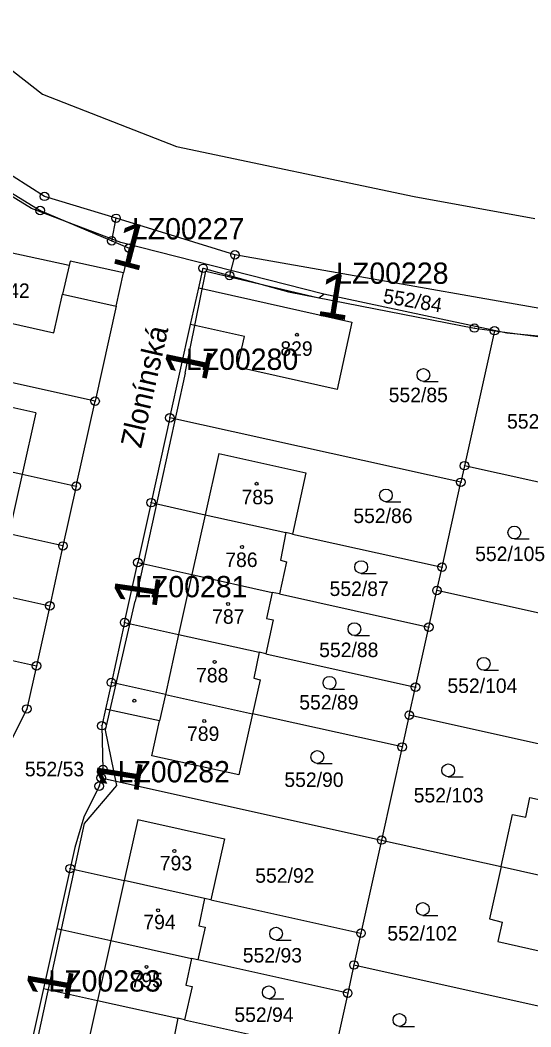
# Model space of a CAD drawing. Extents: x -738131 to -734179, y -1033447 to -1030078.
# Drawn here: x -735624.4 to -735564.5, y -1032052.3 to -1031934.1 of the extents above; entities that cross this region are included whole.
import ezdxf

# ---------------------------------------------------------------- set-up
doc = ezdxf.new("R2010")
doc.units = 0
for name, color, linetype in [('ftf_2010', 7, 'Continuous'), ('ftf_3010', 7, 'Continuous'), ('ftf_3010_ftf_3010_gtda_3015_gtda_3015_1', 7, 'Continuous'), ('ftf_nu', 7, 'Continuous'), ('Vrstva 1', 7, 'Continuous'), ('Vrstva 2', 7, 'Continuous'), ('Vrstva 3', 7, 'Continuous'), ('Vrstva 4', 7, 'Continuous'), ('Vrstva 5', 7, 'Continuous'), ('Vrstva 8', 7, 'Continuous')]:
    doc.layers.add(name, color=color, linetype=linetype)

msp = doc.modelspace()

# ---------------------------------------------------------------- linework, layer by layer
at = {"layer": 'ftf_2010'}
for points in [[(-735612.61, -1031960.22), (-735623.09, -1031956.22), (-735631.82, -1031950.86), (-735637.01, -1031946.51), (-735639.19, -1031944.26)], [(-735588.76, -1031966.29), (-735612.61, -1031960.22)], [(-735605.04, -1031975.54), (-735602.63, -1031963.58), (-735589.35, -1031966.7), (-735588.76, -1031966.29)], [(-735561.58, -1031971.42), (-735567.29, -1031970.85), (-735588.76, -1031966.29)], [(-735605.04, -1031975.54), (-735610.94, -1032002.29)], [(-735613.07, -1032023.94), (-735614.43, -1032017.46), (-735610.94, -1032002.29)], [(-735621.24, -1032048.4), (-735616.9, -1032028.4), (-735613.07, -1032023.94)], [(-735626.37, -1032072.12), (-735621.24, -1032048.4)]]:
    msp.add_lwpolyline(points, dxfattribs=at)
at = {"layer": 'Vrstva 1'}
for points in [[(-735632.99, -1031934.13), (-735621.82, -1031942.82)], [(-735621.82, -1031942.82), (-735606.06, -1031948.94)], [(-735621.58, -1031954.81), (-735632.67, -1031947.8)], [(-735606.06, -1031948.94), (-735578.16, -1031954.83)], [(-735632.24, -1031950.25), (-735622.08, -1031956.47)], [(-735613.18, -1031957.38), (-735621.58, -1031954.81)], [(-735578.16, -1031954.83), (-735563.98, -1031957.41)], [(-735622.08, -1031956.47), (-735613.69, -1031960.02)], [(-735613.69, -1031960.02), (-735613.18, -1031957.38)], [(-735599.21, -1031961.66), (-735613.18, -1031957.38)], [(-735613.69, -1031960.02), (-735611.65, -1031960.88)], [(-735618.67, -1031962.92), (-735630.47, -1031960.38)], [(-735611.65, -1031960.88), (-735612.3, -1031963.79)], [(-735618.56, -1031962.41), (-735618.67, -1031962.92)], [(-735612.3, -1031963.79), (-735618.56, -1031962.41)], [(-735599.21, -1031961.66), (-735599.84, -1031964.11)], [(-735549.41, -1031970.43), (-735599.21, -1031961.66)], [(-735603.47, -1031965.55), (-735602.96, -1031963.25)], [(-735602.96, -1031963.25), (-735599.84, -1031964.11)], [(-735613.16, -1031967.7), (-735612.3, -1031963.79)], [(-735599.84, -1031964.11), (-735592.94, -1031966)], [(-735604.42, -1031969.83), (-735603.47, -1031965.55)], [(-735603.47, -1031965.55), (-735585.48, -1031969.59)], [(-735620.49, -1031970.84), (-735619.45, -1031966.29)], [(-735619.45, -1031966.29), (-735613.16, -1031967.7)], [(-735592.94, -1031966), (-735571.09, -1031970.26)], [(-735632.16, -1031968.19), (-735620.49, -1031970.84)], [(-735613.16, -1031967.7), (-735615.64, -1031978.85)], [(-735606.85, -1031980.8), (-735604.42, -1031969.83)], [(-735598.1, -1031971.24), (-735604.42, -1031969.83)], [(-735585.48, -1031969.59), (-735587.19, -1031977.48)], [(-735568.73, -1031970.57), (-735572.25, -1031986.41)], [(-735571.09, -1031970.26), (-735568.73, -1031970.57)], [(-735568.73, -1031970.57), (-735549.83, -1031973.07)], [(-735615.64, -1031978.85), (-735648.83, -1031971.47)], [(-735598.91, -1031974.87), (-735598.1, -1031971.24)], [(-735587.19, -1031977.48), (-735598.91, -1031974.87)], [(-735622.59, -1031980.2), (-735632.85, -1031977.94)], [(-735617.85, -1031988.81), (-735615.64, -1031978.85)], [(-735622.59, -1031980.2), (-735624.19, -1031987.4)], [(-735606.85, -1031980.8), (-735609.06, -1031990.75)], [(-735572.68, -1031988.36), (-735606.85, -1031980.8)], [(-735633.71, -1031985.28), (-735624.19, -1031987.4)], [(-735601.12, -1031984.97), (-735602.71, -1031992.16)], [(-735601.12, -1031984.97), (-735590.89, -1031987.24)], [(-735572.25, -1031986.41), (-735572.68, -1031988.36)], [(-735540.03, -1031993.56), (-735572.25, -1031986.41)], [(-735624.19, -1031987.4), (-735617.85, -1031988.81)], [(-735590.89, -1031987.24), (-735592.47, -1031994.43)], [(-735574.89, -1031998.32), (-735572.68, -1031988.36)], [(-735617.85, -1031988.81), (-735619.41, -1031995.83)], [(-735609.06, -1031990.75), (-735610.61, -1031997.78)], [(-735609.06, -1031990.75), (-735602.71, -1031992.16)], [(-735602.71, -1031992.16), (-735593.23, -1031994.26)], [(-735593.23, -1031994.26), (-735593.88, -1031997.51)], [(-735592.47, -1031994.43), (-735593.23, -1031994.26)], [(-735619.41, -1031995.83), (-735625.76, -1031994.42)], [(-735592.47, -1031994.43), (-735574.89, -1031998.32)], [(-735619.41, -1031995.83), (-735620.96, -1032002.86)], [(-735612.17, -1032004.81), (-735610.61, -1031997.78)], [(-735610.61, -1031997.78), (-735604.27, -1031999.19)], [(-735593.15, -1031997.68), (-735594, -1032001.46)], [(-735593.88, -1031997.51), (-735593.15, -1031997.68)], [(-735575.49, -1032001.05), (-735574.89, -1031998.32)], [(-735604.27, -1031999.19), (-735594.84, -1032001.28)], [(-735594.84, -1032001.28), (-735595.51, -1032004.33)], [(-735594, -1032001.46), (-735594.84, -1032001.28)], [(-735576.45, -1032005.35), (-735575.49, -1032001.05)], [(-735561.39, -1032004.18), (-735575.49, -1032001.05)], [(-735627.33, -1032001.45), (-735620.96, -1032002.86)], [(-735594, -1032001.46), (-735576.45, -1032005.35)], [(-735620.96, -1032002.86), (-735622.52, -1032009.89)], [(-735612.17, -1032004.81), (-735613.73, -1032011.84)], [(-735612.17, -1032004.81), (-735605.83, -1032006.22)], [(-735594.72, -1032004.5), (-735595.58, -1032008.49)], [(-735595.51, -1032004.33), (-735594.72, -1032004.5)], [(-735578.01, -1032012.39), (-735576.45, -1032005.35)], [(-735605.83, -1032006.22), (-735596.38, -1032008.31)], [(-735628.89, -1032008.48), (-735622.52, -1032009.89)], [(-735596.38, -1032008.31), (-735597, -1032011.35)], [(-735595.58, -1032008.49), (-735596.38, -1032008.31)], [(-735595.58, -1032008.49), (-735578.01, -1032012.39)], [(-735622.52, -1032009.89), (-735623.65, -1032014.96)], [(-735613.73, -1032011.84), (-735614.42, -1032014.97)], [(-735607.38, -1032013.25), (-735613.73, -1032011.84)], [(-735596.24, -1032011.52), (-735597.14, -1032015.52)], [(-735597, -1032011.35), (-735596.24, -1032011.52)], [(-735578.74, -1032015.68), (-735578.01, -1032012.39)], [(-735607.38, -1032013.25), (-735597.14, -1032015.52)], [(-735623.65, -1032014.96), (-735625.96, -1032019.58)], [(-735614.42, -1032014.97), (-735614.85, -1032016.92)], [(-735608.07, -1032016.35), (-735614.42, -1032014.97)], [(-735597.14, -1032015.52), (-735598.74, -1032022.69)], [(-735579.57, -1032019.42), (-735597.14, -1032015.52)], [(-735608.98, -1032020.44), (-735608.07, -1032016.35)], [(-735578.74, -1032015.68), (-735579.57, -1032019.42)], [(-735546.53, -1032022.85), (-735578.74, -1032015.68)], [(-735614.85, -1032016.92), (-735614.71, -1032022.06)], [(-735579.57, -1032019.42), (-735581.99, -1032030.34)], [(-735598.74, -1032022.69), (-735608.98, -1032020.44)], [(-735614.71, -1032022.06), (-735614.93, -1032023.04)], [(-735614.93, -1032023.04), (-735615.15, -1032024.01)], [(-735614.93, -1032023.04), (-735581.99, -1032030.34)], [(-735615.15, -1032024.01), (-735616.96, -1032027.64)], [(-735565.07, -1032027.66), (-735564.59, -1032025.33)], [(-735564.59, -1032025.33), (-735555.21, -1032027.4)], [(-735567.95, -1032033.46), (-735566.6, -1032027.35)], [(-735566.6, -1032027.35), (-735565.07, -1032027.66)], [(-735616.96, -1032027.64), (-735618.03, -1032031.22)], [(-735610.63, -1032027.93), (-735612.23, -1032035.1)], [(-735610.63, -1032027.93), (-735600.44, -1032030.2)], [(-735600.44, -1032030.2), (-735602.04, -1032037.36)], [(-735581.99, -1032030.34), (-735584.41, -1032041.27)], [(-735581.99, -1032030.34), (-735567.95, -1032033.46)], [(-735618.03, -1032031.22), (-735618.57, -1032033.69)], [(-735618.57, -1032033.69), (-735620.14, -1032040.72)], [(-735618.57, -1032033.69), (-735612.23, -1032035.1)], [(-735567.95, -1032033.46), (-735569.31, -1032039.58)], [(-735567.95, -1032033.46), (-735549.77, -1032037.5)], [(-735602.79, -1032037.19), (-735612.23, -1032035.1)], [(-735602.79, -1032037.19), (-735603.45, -1032040.41)], [(-735602.04, -1032037.36), (-735602.79, -1032037.19)], [(-735602.04, -1032037.36), (-735584.41, -1032041.27)], [(-735569.31, -1032039.58), (-735567.83, -1032039.96)], [(-735567.83, -1032039.96), (-735568.33, -1032042.23)], [(-735620.14, -1032040.72), (-735621.7, -1032047.76)], [(-735620.14, -1032040.72), (-735613.79, -1032042.13)], [(-735602.73, -1032040.56), (-735603.58, -1032044.39)], [(-735603.45, -1032040.41), (-735602.73, -1032040.56)], [(-735584.41, -1032041.27), (-735585.24, -1032045)], [(-735613.79, -1032042.13), (-735604.32, -1032044.23)], [(-735568.33, -1032042.23), (-735558.98, -1032044.34)], [(-735604.32, -1032044.23), (-735605, -1032047.36)], [(-735603.58, -1032044.39), (-735604.32, -1032044.23)], [(-735585.97, -1032048.3), (-735603.58, -1032044.39)], [(-735585.24, -1032045), (-735585.97, -1032048.3)], [(-735585.24, -1032045), (-735553.02, -1032052.12)], [(-735605, -1032047.36), (-735604.25, -1032047.52)], [(-735621.7, -1032047.76), (-735623.26, -1032054.79)], [(-735621.7, -1032047.76), (-735615.36, -1032049.17)], [(-735604.25, -1032047.52), (-735605.12, -1032051.43)], [(-735585.97, -1032048.3), (-735587.53, -1032055.33)], [(-735615.36, -1032049.17), (-735605.94, -1032051.25)], [(-735605.94, -1032051.25), (-735606.54, -1032054.35)], [(-735605.12, -1032051.43), (-735605.94, -1032051.25)], [(-735605.12, -1032051.43), (-735587.53, -1032055.33)]]:
    msp.add_lwpolyline(points, dxfattribs=at)
at = {"layer": 'Vrstva 3'}
for p, q in [((-735577.08, -1031976.52), (-735575.33, -1031976.52)), ((-735581.48, -1031990.65), (-735579.73, -1031990.65)), ((-735566.4, -1031995), (-735564.65, -1031995)), ((-735584.39, -1031999.06), (-735582.64, -1031999.06)), ((-735585.18, -1032006.34), (-735583.43, -1032006.34)), ((-735570, -1032010.41), (-735568.25, -1032010.41)), ((-735588.11, -1032012.64), (-735586.36, -1032012.64)), ((-735589.54, -1032021.35), (-735587.79, -1032021.35)), ((-735574.17, -1032022.91), (-735572.42, -1032022.91)), ((-735577.15, -1032039.18), (-735575.4, -1032039.18)), ((-735594.38, -1032042.08), (-735592.63, -1032042.08)), ((-735595.24, -1032048.96), (-735593.49, -1032048.96)), ((-735579.89, -1032052.2), (-735578.14, -1032052.2))]:
    msp.add_line(p, q, dxfattribs=at)
for centre in [(-735577.08, -1031975.77), (-735581.48, -1031989.9), (-735566.4, -1031994.25), (-735584.39, -1031998.31), (-735585.18, -1032005.59), (-735570, -1032009.66), (-735588.11, -1032011.89), (-735589.54, -1032020.6), (-735574.17, -1032022.16), (-735577.15, -1032038.43), (-735594.38, -1032041.33), (-735595.24, -1032048.21), (-735579.89, -1032051.45)]:
    msp.add_circle(centre, 0.75, dxfattribs=at)
at = {"layer": 'Vrstva 4'}
for points in [[(-735618.67, -1031962.92), (-735619.45, -1031966.29)], [(-735624.19, -1031987.4), (-735625.76, -1031994.42)], [(-735602.71, -1031992.16), (-735604.27, -1031999.19)], [(-735604.27, -1031999.19), (-735605.83, -1032006.22)], [(-735605.83, -1032006.22), (-735607.38, -1032013.25)], [(-735607.38, -1032013.25), (-735608.07, -1032016.35)], [(-735612.23, -1032035.1), (-735613.79, -1032042.13)], [(-735613.79, -1032042.13), (-735615.36, -1032049.17)], [(-735615.36, -1032049.17), (-735616.92, -1032056.19)]]:
    msp.add_lwpolyline(points, dxfattribs=at)
at = {"layer": 'Vrstva 5'}
for centre in [(-735591.94, -1031971.05), (-735596.68, -1031988.53), (-735598.38, -1031995.95), (-735600.02, -1032002.64), (-735601.6, -1032009.44), (-735611.03, -1032014), (-735602.82, -1032016.37), (-735606.33, -1032031.62), (-735608.24, -1032038.58), (-735609.6, -1032045.22)]:
    msp.add_circle(centre, 0.175, dxfattribs=at)
at = {"layer": 'Vrstva 8'}
for centre, radius in [((-735621.58, -1031954.81), 0.5), ((-735621.58, -1031954.81), 0.0303), ((-735622.08, -1031956.47), 0.5), ((-735622.08, -1031956.47), 0.0303), ((-735613.18, -1031957.38), 0.5), ((-735613.18, -1031957.38), 0.0303), ((-735613.69, -1031960.02), 0.5), ((-735613.69, -1031960.02), 0.0303), ((-735611.65, -1031960.88), 0.5), ((-735611.65, -1031960.88), 0.0303), ((-735599.21, -1031961.66), 0.5), ((-735599.21, -1031961.66), 0.0303), ((-735602.96, -1031963.25), 0.5), ((-735602.96, -1031963.25), 0.0303), ((-735599.84, -1031964.11), 0.5), ((-735599.84, -1031964.11), 0.0303), ((-735571.09, -1031970.26), 0.5), ((-735571.09, -1031970.26), 0.0303), ((-735568.73, -1031970.57), 0.5), ((-735568.73, -1031970.57), 0.0303), ((-735615.64, -1031978.85), 0.5), ((-735615.64, -1031978.85), 0.0303), ((-735606.85, -1031980.8), 0.5), ((-735606.85, -1031980.8), 0.0303), ((-735572.25, -1031986.41), 0.5), ((-735572.25, -1031986.41), 0.0303), ((-735617.85, -1031988.81), 0.5), ((-735572.68, -1031988.36), 0.5), ((-735572.68, -1031988.36), 0.0303), ((-735617.85, -1031988.81), 0.0303), ((-735609.06, -1031990.75), 0.5), ((-735609.06, -1031990.75), 0.0303), ((-735619.41, -1031995.83), 0.5), ((-735619.41, -1031995.83), 0.0303), ((-735610.61, -1031997.78), 0.5), ((-735610.61, -1031997.78), 0.0303), ((-735574.89, -1031998.32), 0.5), ((-735574.89, -1031998.32), 0.0303), ((-735575.49, -1032001.05), 0.5), ((-735575.49, -1032001.05), 0.0303), ((-735620.96, -1032002.86), 0.5), ((-735620.96, -1032002.86), 0.0303), ((-735612.17, -1032004.81), 0.5), ((-735612.17, -1032004.81), 0.0303), ((-735576.45, -1032005.35), 0.5), ((-735576.45, -1032005.35), 0.0303), ((-735622.52, -1032009.89), 0.5), ((-735622.52, -1032009.89), 0.0303), ((-735613.73, -1032011.84), 0.5), ((-735613.73, -1032011.84), 0.0303), ((-735578.01, -1032012.39), 0.5), ((-735578.01, -1032012.39), 0.0303), ((-735623.65, -1032014.96), 0.5), ((-735623.65, -1032014.96), 0.0303), ((-735578.74, -1032015.68), 0.5), ((-735614.85, -1032016.92), 0.5), ((-735578.74, -1032015.68), 0.0303), ((-735614.85, -1032016.92), 0.0303), ((-735579.57, -1032019.42), 0.5), ((-735579.57, -1032019.42), 0.0303), ((-735614.93, -1032023.04), 0.5), ((-735614.71, -1032022.06), 0.5), ((-735614.71, -1032022.06), 0.0303), ((-735615.15, -1032024.01), 0.5), ((-735614.93, -1032023.04), 0.0303), ((-735615.15, -1032024.01), 0.0303), ((-735581.99, -1032030.34), 0.5), ((-735581.99, -1032030.34), 0.0303), ((-735618.57, -1032033.69), 0.5), ((-735618.57, -1032033.69), 0.0303), ((-735584.41, -1032041.27), 0.5), ((-735584.41, -1032041.27), 0.0303), ((-735585.24, -1032045), 0.5), ((-735585.24, -1032045), 0.0303), ((-735585.97, -1032048.3), 0.5), ((-735585.97, -1032048.3), 0.0303)]:
    msp.add_circle(centre, radius, dxfattribs=at)

# ---------------------------------------------------------------- texts
at = {"layer": 'ftf_3010'}
for rotation, p in [(345.2107, (-735613.9, -1031962.57)), (351.0643, (-735589.8, -1031968.76)), (78.1156, (-735602.63, -1031976.71)), (81.9049, (-735608.45, -1032003.3)), (80.9604, (-735610.61, -1032024.99)), (79.9278, (-735618.79, -1032049.49))]:
    msp.add_text('1', height=5.2, rotation=rotation, dxfattribs=at).set_placement(p)
at = {"layer": 'ftf_3010_ftf_3010_gtda_3015_gtda_3015_1'}
for s, p in [('LZ00227', (-735611.31, -1031959.86)), ('LZ00228', (-735587.33, -1031965.07)), ('LZ00280', (-735604.98, -1031975.17)), ('LZ00281', (-735610.94, -1032001.85)), ('LZ00282', (-735613, -1032023.57)), ('LZ00283', (-735621.13, -1032048.12))]:
    msp.add_text(s, height=2.5, dxfattribs=at).set_placement(p)
at = {"layer": 'ftf_nu'}
msp.add_text('Zlonínská', height=2.5, rotation=77.1509, dxfattribs=at).set_placement((-735610.23, -1031984.46))
at = {"layer": 'Vrstva 2'}
for s, p in [('842', (-735627.11, -1031966.73)), ('829', (-735593.88, -1031973.52)), ('552/85', (-735581.16, -1031978.96)), ('552/106', (-735567.26, -1031982.06)), ('785', (-735598.44, -1031990.94)), ('552/86', (-735585.31, -1031993.14)), ('786', (-735600.35, -1031998.3)), ('552/105', (-735571, -1031997.6)), ('552/87', (-735588.1, -1032001.7)), ('787', (-735601.89, -1032004.96)), ('552/88', (-735589.32, -1032008.87)), ('788', (-735603.78, -1032011.84)), ('552/104', (-735574.26, -1032013.08)), ('552/89', (-735591.66, -1032015.02)), ('789', (-735604.84, -1032018.71)), ('552/53', (-735623.88, -1032022.86)), ('552/90', (-735593.41, -1032024.11)), ('552/103', (-735578.22, -1032025.93)), ('793', (-735608.04, -1032033.9)), ('552/92', (-735596.83, -1032035.35)), ('794', (-735609.97, -1032040.81)), ('552/102', (-735581.32, -1032042.13)), ('552/93', (-735598.29, -1032044.71)), ('795', (-735611.48, -1032047.61)), ('552/94', (-735599.28, -1032051.68))]:
    msp.add_text(s, height=1.7, dxfattribs=at).set_placement(p)
msp.add_text('552/84', height=1.7, rotation=350.3884, dxfattribs=at).set_placement((-735581.91, -1031967.29))

doc.saveas('drawing.dxf')
